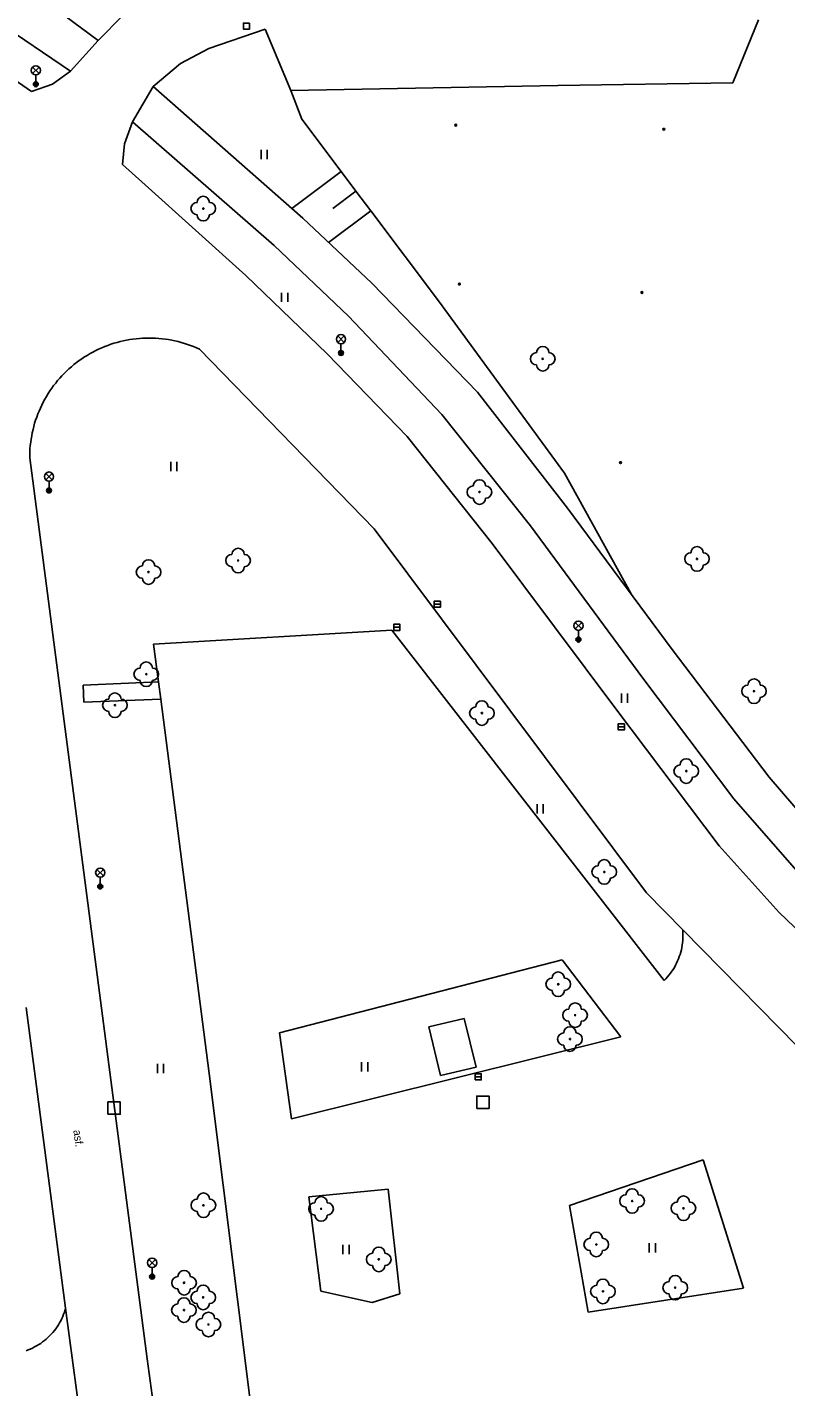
# Model space of a CAD drawing. Extents: x -641829 to -641525, y -1114855 to -1114359.
# Drawn here: x -641724.9 to -641663.2, y -1114535.8 to -1114425.4 of the extents above; entities that cross this region are included whole.
import ezdxf

# ---------------------------------------------------------------- set-up
doc = ezdxf.new("R2010")
doc.units = 0
for name, color, linetype in [('Vrstva 10', 7, 'Continuous'), ('Vrstva 11', 7, 'Continuous'), ('Vrstva 14', 7, 'Continuous'), ('Vrstva 15', 7, 'Continuous'), ('Vrstva 20', 7, 'Continuous'), ('Vrstva 22', 7, 'Continuous'), ('Vrstva 26', 7, 'Continuous'), ('Vrstva 27', 7, 'Continuous'), ('Vrstva 33', 7, 'Continuous'), ('Vrstva 36', 7, 'Continuous'), ('Vrstva 40', 7, 'Continuous')]:
    doc.layers.add(name, color=color, linetype=linetype)

msp = doc.modelspace()

# ---------------------------------------------------------------- linework, layer by layer
at = {"layer": 'Vrstva 10'}
for p, q in [((-641719.11, -1114426.51), (-641717.06, -1114424.45)), ((-641665.47, -1114424.84), (-641667.56, -1114429.94)), ((-641705.53, -1114425.59), (-641710.11, -1114427.15)), ((-641703.46, -1114430.56), (-641705.53, -1114425.59)), ((-641730.26, -1114426.67), (-641724.52, -1114430.66)), ((-641721.35, -1114428.99), (-641719.11, -1114426.51)), ((-641710.11, -1114427.15), (-641712.42, -1114428.39)), ((-641722.8, -1114430.06), (-641721.35, -1114428.99)), ((-641712.42, -1114428.39), (-641714.62, -1114430.25)), ((-641724.52, -1114430.66), (-641722.8, -1114430.06)), ((-641716.31, -1114433.12), (-641714.62, -1114430.25)), ((-641681.77, -1114430.17), (-641703.46, -1114430.56)), ((-641667.56, -1114429.94), (-641681.77, -1114430.17)), ((-641716.31, -1114433.12), (-641716.95, -1114434.91)), ((-641716.95, -1114434.91), (-641717.11, -1114436.59)), ((-641717.11, -1114436.59), (-641715.27, -1114438.22)), ((-641715.27, -1114438.22), (-641707.1, -1114445.6)), ((-641707.1, -1114445.6), (-641700.5, -1114451.95)), ((-641718.57, -1114451.37), (-641718.81, -1114451.47)), ((-641718.32, -1114451.27), (-641718.57, -1114451.37)), ((-641718.08, -1114451.18), (-641718.32, -1114451.27)), ((-641717.82, -1114451.1), (-641718.08, -1114451.18)), ((-641717.57, -1114451.03), (-641717.82, -1114451.1)), ((-641717.31, -1114450.96), (-641717.57, -1114451.03)), ((-641717.06, -1114450.9), (-641717.31, -1114450.96)), ((-641716.8, -1114450.85), (-641717.06, -1114450.9)), ((-641716.54, -1114450.8), (-641716.8, -1114450.85)), ((-641716.28, -1114450.76), (-641716.54, -1114450.8)), ((-641716.02, -1114450.73), (-641716.28, -1114450.76)), ((-641715.75, -1114450.7), (-641716.02, -1114450.73)), ((-641715.49, -1114450.69), (-641715.75, -1114450.7)), ((-641715.23, -1114450.68), (-641715.49, -1114450.69)), ((-641714.96, -1114450.67), (-641715.23, -1114450.68)), ((-641714.7, -1114450.68), (-641714.96, -1114450.67)), ((-641714.43, -1114450.69), (-641714.7, -1114450.68)), ((-641714.17, -1114450.7), (-641714.43, -1114450.69)), ((-641713.91, -1114450.73), (-641714.17, -1114450.7)), ((-641713.64, -1114450.76), (-641713.91, -1114450.73)), ((-641713.38, -1114450.8), (-641713.64, -1114450.76)), ((-641713.12, -1114450.85), (-641713.38, -1114450.8)), ((-641712.86, -1114450.9), (-641713.12, -1114450.85)), ((-641712.61, -1114450.96), (-641712.86, -1114450.9)), ((-641712.35, -1114451.03), (-641712.61, -1114450.96)), ((-641712.1, -1114451.11), (-641712.35, -1114451.03)), ((-641711.85, -1114451.19), (-641712.1, -1114451.11)), ((-641711.6, -1114451.27), (-641711.85, -1114451.19)), ((-641711.35, -1114451.37), (-641711.6, -1114451.27)), ((-641711.11, -1114451.47), (-641711.35, -1114451.37)), ((-641720.65, -1114452.51), (-641720.86, -1114452.67)), ((-641720.43, -1114452.36), (-641720.65, -1114452.51)), ((-641720.21, -1114452.21), (-641720.43, -1114452.36)), ((-641719.99, -1114452.08), (-641720.21, -1114452.21)), ((-641719.76, -1114451.94), (-641719.99, -1114452.08)), ((-641719.53, -1114451.81), (-641719.76, -1114451.94)), ((-641719.29, -1114451.69), (-641719.53, -1114451.81)), ((-641719.06, -1114451.58), (-641719.29, -1114451.69)), ((-641718.81, -1114451.47), (-641719.06, -1114451.58)), ((-641710.87, -1114451.58), (-641711.11, -1114451.47)), ((-641710.87, -1114451.58), (-641696.68, -1114466.16)), ((-641700.5, -1114451.95), (-641694, -1114458.66)), ((-641721.85, -1114453.54), (-641722.04, -1114453.73)), ((-641721.66, -1114453.36), (-641721.85, -1114453.54)), ((-641721.47, -1114453.18), (-641721.66, -1114453.36)), ((-641721.27, -1114453), (-641721.47, -1114453.18)), ((-641721.07, -1114452.83), (-641721.27, -1114453)), ((-641720.86, -1114452.67), (-641721.07, -1114452.83)), ((-641722.87, -1114454.75), (-641723.02, -1114454.97)), ((-641722.72, -1114454.54), (-641722.87, -1114454.75)), ((-641722.55, -1114454.33), (-641722.72, -1114454.54)), ((-641722.39, -1114454.13), (-641722.55, -1114454.33)), ((-641722.21, -1114453.93), (-641722.39, -1114454.13)), ((-641722.04, -1114453.73), (-641722.21, -1114453.93)), ((-641723.44, -1114455.65), (-641723.56, -1114455.88)), ((-641723.3, -1114455.42), (-641723.44, -1114455.65)), ((-641723.17, -1114455.19), (-641723.3, -1114455.42)), ((-641723.02, -1114454.97), (-641723.17, -1114455.19)), ((-641724, -1114456.84), (-641724.09, -1114457.09)), ((-641723.9, -1114456.6), (-641724, -1114456.84)), ((-641723.79, -1114456.36), (-641723.9, -1114456.6)), ((-641723.68, -1114456.12), (-641723.79, -1114456.36)), ((-641723.56, -1114455.88), (-641723.68, -1114456.12)), ((-641724.33, -1114457.85), (-641724.39, -1114458.1)), ((-641724.26, -1114457.59), (-641724.33, -1114457.85)), ((-641724.18, -1114457.34), (-641724.26, -1114457.59)), ((-641724.09, -1114457.09), (-641724.18, -1114457.34)), ((-641724.58, -1114459.14), (-641724.61, -1114459.4)), ((-641724.55, -1114458.88), (-641724.58, -1114459.14)), ((-641724.5, -1114458.62), (-641724.55, -1114458.88)), ((-641724.45, -1114458.36), (-641724.5, -1114458.62)), ((-641724.39, -1114458.1), (-641724.45, -1114458.36)), ((-641694, -1114458.66), (-641687.1, -1114467.37)), ((-641724.65, -1114459.93), (-641724.66, -1114460.2)), ((-641724.66, -1114460.2), (-641724.66, -1114460.41)), ((-641724.64, -1114459.67), (-641724.65, -1114459.93)), ((-641724.61, -1114459.4), (-641724.64, -1114459.67)), ((-641715.11, -1114533.57), (-641724.66, -1114460.41)), ((-641696.68, -1114466.16), (-641674.57, -1114495.73)), ((-641687.1, -1114467.37), (-641676.97, -1114480.89)), ((-641695.26, -1114474.39), (-641714.6, -1114475.54)), ((-641673.13, -1114502.84), (-641695.26, -1114474.39)), ((-641714.6, -1114475.54), (-641714.2, -1114478.59)), ((-641714.2, -1114478.59), (-641714.02, -1114479.99)), ((-641714.02, -1114479.99), (-641710.09, -1114510.39)), ((-641676.97, -1114480.89), (-641668.66, -1114491.92)), ((-641668.66, -1114491.92), (-641663.78, -1114497.32)), ((-641674.57, -1114495.73), (-641671.62, -1114498.73)), ((-641663.78, -1114497.32), (-641659.26, -1114501.67)), ((-641671.62, -1114498.73), (-641659.47, -1114511.09)), ((-641671.61, -1114498.82), (-641671.62, -1114498.73)), ((-641671.6, -1114499.01), (-641671.61, -1114498.82)), ((-641671.69, -1114500.16), (-641671.66, -1114499.97)), ((-641671.66, -1114499.97), (-641671.63, -1114499.78)), ((-641671.63, -1114499.78), (-641671.61, -1114499.59)), ((-641671.61, -1114499.59), (-641671.6, -1114499.4)), ((-641671.6, -1114499.2), (-641671.6, -1114499.01)), ((-641671.6, -1114499.4), (-641671.6, -1114499.2)), ((-641672.04, -1114501.26), (-641671.97, -1114501.09)), ((-641671.97, -1114501.09), (-641671.9, -1114500.9)), ((-641671.9, -1114500.9), (-641671.84, -1114500.72)), ((-641671.84, -1114500.72), (-641671.78, -1114500.54)), ((-641671.78, -1114500.54), (-641671.73, -1114500.35)), ((-641671.73, -1114500.35), (-641671.69, -1114500.16)), ((-641681.41, -1114501.18), (-641704.38, -1114507.1)), ((-641676.64, -1114507.41), (-641681.41, -1114501.18)), ((-641672.62, -1114502.26), (-641672.51, -1114502.1)), ((-641672.51, -1114502.1), (-641672.4, -1114501.94)), ((-641672.4, -1114501.94), (-641672.3, -1114501.78)), ((-641672.3, -1114501.78), (-641672.21, -1114501.61)), ((-641672.21, -1114501.61), (-641672.12, -1114501.44)), ((-641672.12, -1114501.44), (-641672.04, -1114501.26)), ((-641673.13, -1114502.84), (-641672.99, -1114502.7)), ((-641672.99, -1114502.7), (-641672.86, -1114502.56)), ((-641672.86, -1114502.56), (-641672.74, -1114502.41)), ((-641672.74, -1114502.41), (-641672.62, -1114502.26)), ((-641724.95, -1114505.04), (-641721.74, -1114529.44)), ((-641704.38, -1114507.1), (-641703.4, -1114514.07)), ((-641676.64, -1114507.41), (-641703.4, -1114514.07)), ((-641710.09, -1114510.39), (-641706.68, -1114537.6)), ((-641680.82, -1114521.12), (-641669.95, -1114517.42)), ((-641669.95, -1114517.42), (-641666.68, -1114527.82)), ((-641695.55, -1114519.79), (-641701.99, -1114520.4)), ((-641694.6, -1114528.3), (-641695.55, -1114519.79)), ((-641701.99, -1114520.4), (-641701.01, -1114528.06)), ((-641679.29, -1114529.77), (-641680.82, -1114521.12)), ((-641701.01, -1114528.06), (-641696.85, -1114528.99)), ((-641696.85, -1114528.99), (-641694.6, -1114528.3)), ((-641679.29, -1114529.77), (-641666.68, -1114527.82)), ((-641721.91, -1114529.95), (-641721.84, -1114529.77)), ((-641721.84, -1114529.77), (-641721.79, -1114529.58)), ((-641721.79, -1114529.58), (-641721.74, -1114529.44)), ((-641720.22, -1114541.01), (-641721.74, -1114529.44)), ((-641722.44, -1114530.96), (-641722.33, -1114530.8)), ((-641722.33, -1114530.8), (-641722.24, -1114530.64)), ((-641722.24, -1114530.64), (-641722.14, -1114530.47)), ((-641722.14, -1114530.47), (-641722.06, -1114530.3)), ((-641722.06, -1114530.3), (-641721.98, -1114530.12)), ((-641721.98, -1114530.12), (-641721.91, -1114529.95)), ((-641723.47, -1114532.08), (-641723.32, -1114531.96)), ((-641723.32, -1114531.96), (-641723.18, -1114531.83)), ((-641723.18, -1114531.83), (-641723.04, -1114531.7)), ((-641723.04, -1114531.7), (-641722.91, -1114531.56)), ((-641722.91, -1114531.56), (-641722.78, -1114531.42)), ((-641722.78, -1114531.42), (-641722.66, -1114531.27)), ((-641722.66, -1114531.27), (-641722.55, -1114531.12)), ((-641722.55, -1114531.12), (-641722.44, -1114530.96)), ((-641724.96, -1114532.91), (-641724.78, -1114532.84)), ((-641724.78, -1114532.84), (-641724.61, -1114532.77)), ((-641724.61, -1114532.77), (-641724.43, -1114532.69)), ((-641724.43, -1114532.69), (-641724.26, -1114532.6)), ((-641724.26, -1114532.6), (-641724.1, -1114532.51)), ((-641724.1, -1114532.51), (-641723.93, -1114532.41)), ((-641723.93, -1114532.41), (-641723.77, -1114532.31)), ((-641723.77, -1114532.31), (-641723.62, -1114532.2)), ((-641723.62, -1114532.2), (-641723.47, -1114532.08)), ((-641710.95, -1114564.98), (-641715.11, -1114533.57))]:
    msp.add_line(p, q, dxfattribs=at)
at = {"layer": 'Vrstva 11'}
for p, q in [((-641721.35, -1114428.99), (-641733.03, -1114421.08)), ((-641719.11, -1114426.51), (-641724.4, -1114422.58)), ((-641702.47, -1114440.95), (-641714.62, -1114430.25)), ((-641704.8, -1114443.15), (-641716.31, -1114433.12)), ((-641696.86, -1114446.22), (-641702.47, -1114440.95)), ((-641698.78, -1114448.89), (-641704.8, -1114443.15)), ((-641688.28, -1114455.08), (-641696.86, -1114446.22)), ((-641691.19, -1114456.88), (-641698.78, -1114448.89)), ((-641680.98, -1114464.5), (-641688.28, -1114455.08)), ((-641683.99, -1114465.91), (-641691.19, -1114456.88)), ((-641672.47, -1114475.96), (-641680.98, -1114464.5)), ((-641674.85, -1114478.28), (-641683.99, -1114465.91)), ((-641664.6, -1114486.32), (-641672.47, -1114475.96)), ((-641714.2, -1114478.59), (-641720.33, -1114478.85)), ((-641720.27, -1114480.25), (-641720.33, -1114478.85)), ((-641667.48, -1114488.09), (-641674.85, -1114478.28)), ((-641714.02, -1114479.99), (-641720.27, -1114480.25)), ((-641660.12, -1114491.55), (-641664.6, -1114486.32)), ((-641662.19, -1114494.13), (-641667.48, -1114488.09)), ((-641689.36, -1114505.94), (-641692.24, -1114506.62)), ((-641692.24, -1114506.62), (-641691.29, -1114510.56)), ((-641689.36, -1114505.94), (-641688.41, -1114509.88)), ((-641688.41, -1114509.88), (-641691.29, -1114510.56))]:
    msp.add_line(p, q, dxfattribs=at)
at = {"layer": 'Vrstva 14'}
for p, q in [((-641702.56, -1114432.89), (-641703.46, -1114430.56)), ((-641699.36, -1114437.15), (-641702.56, -1114432.89)), ((-641698.16, -1114438.74), (-641699.36, -1114437.15)), ((-641696.96, -1114440.34), (-641698.16, -1114438.74)), ((-641691.47, -1114447.64), (-641696.96, -1114440.34)), ((-641681.21, -1114461.64), (-641691.47, -1114447.64)), ((-641675.82, -1114471.45), (-641681.21, -1114461.64))]:
    msp.add_line(p, q, dxfattribs=at)
at = {"layer": 'Vrstva 15'}
for p, q in [((-641703.37, -1114440.16), (-641699.36, -1114437.15)), ((-641700.04, -1114440.16), (-641698.16, -1114438.74)), ((-641700.38, -1114442.91), (-641696.96, -1114440.34))]:
    msp.add_line(p, q, dxfattribs=at)
at = {"layer": 'Vrstva 20'}
for centre, radius in [((-641690.06, -1114433.39), 0.075), ((-641690.06, -1114433.39), 0.0204), ((-641673.16, -1114433.72), 0.075), ((-641673.16, -1114433.72), 0.0204), ((-641689.76, -1114446.29), 0.075), ((-641689.76, -1114446.29), 0.0204), ((-641674.93, -1114446.97), 0.075), ((-641674.93, -1114446.97), 0.0204), ((-641676.67, -1114460.79), 0.075), ((-641676.67, -1114460.79), 0.0204)]:
    msp.add_circle(centre, radius, dxfattribs=at)
at = {"layer": 'Vrstva 22'}
for centre in [(-641710.56, -1114440.16), (-641682.99, -1114452.36), (-641688.13, -1114463.18), (-641707.73, -1114468.74), (-641670.46, -1114468.61), (-641715.01, -1114469.68), (-641715.19, -1114477.97), (-641665.83, -1114479.35), (-641717.74, -1114480.49), (-641687.93, -1114481.13), (-641671.33, -1114485.84), (-641677.99, -1114494.03), (-641681.73, -1114503.15), (-641680.36, -1114505.66), (-641680.78, -1114507.6), (-641675.73, -1114520.75), (-641710.55, -1114521.1), (-641700.99, -1114521.39), (-641671.56, -1114521.34), (-641678.64, -1114524.28), (-641696.31, -1114525.49), (-641712.12, -1114527.39), (-641710.57, -1114528.58), (-641678.1, -1114528.09), (-641672.23, -1114527.79), (-641712.13, -1114529.61), (-641710.14, -1114530.78)]:
    msp.add_circle(centre, 0.05, dxfattribs=at)
for centre, start, end in [((-641710.56, -1114439.66), 0, 180), ((-641711.06, -1114440.16), 90, 270), ((-641710.06, -1114440.16), 270, 90), ((-641710.56, -1114440.66), 180, 0), ((-641682.99, -1114451.86), 0, 180), ((-641683.49, -1114452.36), 90, 270), ((-641682.49, -1114452.36), 270, 90), ((-641682.99, -1114452.86), 180, 0), ((-641688.13, -1114462.68), 0, 180), ((-641688.63, -1114463.18), 90, 270), ((-641687.63, -1114463.18), 270, 90), ((-641688.13, -1114463.68), 180, 0), ((-641707.73, -1114468.24), 0, 180), ((-641670.46, -1114468.11), 0, 180), ((-641715.01, -1114469.18), 0, 180), ((-641708.23, -1114468.74), 90, 270), ((-641707.23, -1114468.74), 270, 90), ((-641670.96, -1114468.61), 90, 270), ((-641670.46, -1114469.11), 180, 0), ((-641669.96, -1114468.61), 270, 90), ((-641715.51, -1114469.68), 90, 270), ((-641715.01, -1114470.18), 180, 0), ((-641714.51, -1114469.68), 270, 90), ((-641707.73, -1114469.24), 180, 0), ((-641715.69, -1114477.97), 90, 270), ((-641715.19, -1114477.47), 0, 180), ((-641714.69, -1114477.97), 270, 90), ((-641715.19, -1114478.47), 180, 0), ((-641666.33, -1114479.35), 90, 270), ((-641665.83, -1114478.85), 0, 180), ((-641665.33, -1114479.35), 270, 90), ((-641718.24, -1114480.49), 90, 270), ((-641717.74, -1114479.99), 0, 180), ((-641717.24, -1114480.49), 270, 90), ((-641687.93, -1114480.63), 0, 180), ((-641665.83, -1114479.85), 180, 0), ((-641717.74, -1114480.99), 180, 0), ((-641688.43, -1114481.13), 90, 270), ((-641687.43, -1114481.13), 270, 90), ((-641687.93, -1114481.63), 180, 0), ((-641671.83, -1114485.84), 90, 270), ((-641671.33, -1114485.34), 0, 180), ((-641670.83, -1114485.84), 270, 90), ((-641671.33, -1114486.34), 180, 0), ((-641677.99, -1114493.53), 0, 180), ((-641678.49, -1114494.03), 90, 270), ((-641677.49, -1114494.03), 270, 90), ((-641677.99, -1114494.53), 180, 0), ((-641681.73, -1114502.65), 0, 180), ((-641682.23, -1114503.15), 90, 270), ((-641681.23, -1114503.15), 270, 90), ((-641681.73, -1114503.65), 180, 0), ((-641680.86, -1114505.66), 90, 270), ((-641680.36, -1114505.16), 0, 180), ((-641679.86, -1114505.66), 270, 90), ((-641680.78, -1114507.1), 0, 180), ((-641680.36, -1114506.16), 180, 0), ((-641681.28, -1114507.6), 90, 270), ((-641680.28, -1114507.6), 270, 90), ((-641680.78, -1114508.1), 180, 0), ((-641675.73, -1114520.25), 0, 180), ((-641711.05, -1114521.1), 90, 270), ((-641710.55, -1114520.6), 0, 180), ((-641710.05, -1114521.1), 270, 90), ((-641701.49, -1114521.39), 90, 270), ((-641700.99, -1114520.89), 0, 180), ((-641700.49, -1114521.39), 270, 90), ((-641676.23, -1114520.75), 90, 270), ((-641675.23, -1114520.75), 270, 90), ((-641672.06, -1114521.34), 90, 270), ((-641671.56, -1114520.84), 0, 180), ((-641671.06, -1114521.34), 270, 90), ((-641710.55, -1114521.6), 180, 0), ((-641700.99, -1114521.89), 180, 0), ((-641675.73, -1114521.25), 180, 0), ((-641671.56, -1114521.84), 180, 0), ((-641679.14, -1114524.28), 90, 270), ((-641678.64, -1114523.78), 0, 180), ((-641678.14, -1114524.28), 270, 90), ((-641696.81, -1114525.49), 90, 270), ((-641696.31, -1114524.99), 0, 180), ((-641695.81, -1114525.49), 270, 90), ((-641678.64, -1114524.78), 180, 0), ((-641712.12, -1114526.89), 0, 180), ((-641696.31, -1114525.99), 180, 0), ((-641712.62, -1114527.39), 90, 270), ((-641711.62, -1114527.39), 270, 90), ((-641710.57, -1114528.08), 0, 180), ((-641678.6, -1114528.09), 90, 270), ((-641678.1, -1114527.59), 0, 180), ((-641677.6, -1114528.09), 270, 90), ((-641672.73, -1114527.79), 90, 270), ((-641672.23, -1114527.29), 0, 180), ((-641671.73, -1114527.79), 270, 90), ((-641712.13, -1114529.11), 0, 180), ((-641712.12, -1114527.89), 180, 0), ((-641711.07, -1114528.58), 90, 270), ((-641710.07, -1114528.58), 270, 90), ((-641678.1, -1114528.59), 180, 0), ((-641672.23, -1114528.29), 180, 0), ((-641712.63, -1114529.61), 90, 270), ((-641711.63, -1114529.61), 270, 90), ((-641710.57, -1114529.08), 180, 0), ((-641710.14, -1114530.28), 0, 180), ((-641712.13, -1114530.11), 180, 0), ((-641710.64, -1114530.78), 90, 270), ((-641709.64, -1114530.78), 270, 90), ((-641710.14, -1114531.28), 180, 0)]:
    msp.add_arc(centre, 0.5, start, end, dxfattribs=at)
at = {"layer": 'Vrstva 26'}
for points in [[(-641718.31, -1114513.7), (-641717.31, -1114513.7), (-641717.31, -1114512.7), (-641718.31, -1114512.7)], [(-641688.35, -1114513.23), (-641687.35, -1114513.23), (-641687.35, -1114512.23), (-641688.35, -1114512.23)]]:
    msp.add_lwpolyline(points, close=True, dxfattribs=at)
at = {"layer": 'Vrstva 27'}
for p, q in [((-641691.3, -1114472.29), (-641691.8, -1114472.29)), ((-641695.09, -1114474.16), (-641694.59, -1114474.16)), ((-641676.36, -1114482.25), (-641676.86, -1114482.25)), ((-641688.48, -1114510.67), (-641687.98, -1114510.67))]:
    msp.add_line(p, q, dxfattribs=at)
for points in [[(-641706.8, -1114425.09), (-641707.3, -1114425.09), (-641707.3, -1114425.59), (-641706.8, -1114425.59)], [(-641691.3, -1114472.04), (-641691.8, -1114472.04), (-641691.8, -1114472.54), (-641691.3, -1114472.54)], [(-641695.09, -1114474.41), (-641694.59, -1114474.41), (-641694.59, -1114473.91), (-641695.09, -1114473.91)], [(-641676.36, -1114482), (-641676.86, -1114482), (-641676.86, -1114482.5), (-641676.36, -1114482.5)], [(-641688.48, -1114510.92), (-641687.98, -1114510.92), (-641687.98, -1114510.42), (-641688.48, -1114510.42)]]:
    msp.add_lwpolyline(points, close=True, dxfattribs=at)
at = {"layer": 'Vrstva 33'}
for p, q in [((-641724.424, -1114429.2), (-641723.896, -1114428.67)), ((-641724.424, -1114428.67), (-641723.896, -1114429.2)), ((-641724.16, -1114429.31), (-641724.16, -1114430.06)), ((-641699.644, -1114451.03), (-641699.116, -1114450.5)), ((-641699.644, -1114450.5), (-641699.116, -1114451.03)), ((-641699.38, -1114451.14), (-641699.38, -1114451.89)), ((-641723.356, -1114462.19), (-641722.824, -1114461.66)), ((-641723.356, -1114461.66), (-641722.824, -1114462.19)), ((-641723.09, -1114462.3), (-641723.09, -1114463.05)), ((-641680.354, -1114474.3), (-641679.826, -1114473.77)), ((-641680.354, -1114473.77), (-641679.826, -1114474.3)), ((-641680.09, -1114474.41), (-641680.09, -1114475.16)), ((-641719.196, -1114494.35), (-641718.664, -1114493.82)), ((-641719.196, -1114493.82), (-641718.664, -1114494.35)), ((-641718.93, -1114494.46), (-641718.93, -1114495.21)), ((-641714.984, -1114526.03), (-641714.456, -1114525.5)), ((-641714.984, -1114525.5), (-641714.456, -1114526.03)), ((-641714.72, -1114526.14), (-641714.72, -1114526.89))]:
    msp.add_line(p, q, dxfattribs=at)
for centre, radius in [((-641724.16, -1114428.935), 0.375), ((-641724.16, -1114430.06), 0.2), ((-641724.16, -1114430.06), 0.145), ((-641724.16, -1114430.06), 0.0876), ((-641699.38, -1114450.765), 0.375), ((-641699.38, -1114451.89), 0.2), ((-641699.38, -1114451.89), 0.145), ((-641699.38, -1114451.89), 0.0876), ((-641723.09, -1114461.925), 0.375), ((-641723.09, -1114463.05), 0.2), ((-641723.09, -1114463.05), 0.145), ((-641723.09, -1114463.05), 0.0876), ((-641680.09, -1114474.035), 0.375), ((-641680.09, -1114475.16), 0.2), ((-641680.09, -1114475.16), 0.145), ((-641680.09, -1114475.16), 0.0876), ((-641718.93, -1114494.085), 0.375), ((-641718.93, -1114495.21), 0.2), ((-641718.93, -1114495.21), 0.145), ((-641718.93, -1114495.21), 0.0876), ((-641714.72, -1114525.765), 0.375), ((-641714.72, -1114526.89), 0.2), ((-641714.72, -1114526.89), 0.145), ((-641714.72, -1114526.89), 0.0876)]:
    msp.add_circle(centre, radius, dxfattribs=at)
at = {"layer": 'Vrstva 36'}
for p, q in [((-641705.864, -1114436.142), (-641705.864, -1114435.394)), ((-641705.364, -1114436.142), (-641705.364, -1114435.394)), ((-641704.204, -1114447.742), (-641704.204, -1114446.994)), ((-641703.704, -1114447.742), (-641703.704, -1114446.994)), ((-641713.204, -1114461.484), (-641713.204, -1114460.732)), ((-641712.704, -1114461.484), (-641712.704, -1114460.732)), ((-641676.604, -1114480.284), (-641676.604, -1114479.532)), ((-641676.104, -1114480.284), (-641676.104, -1114479.532)), ((-641683.444, -1114489.274), (-641683.444, -1114488.522)), ((-641682.944, -1114489.274), (-641682.944, -1114488.522)), ((-641714.294, -1114510.362), (-641714.294, -1114509.614)), ((-641713.794, -1114510.362), (-641713.794, -1114509.614)), ((-641697.704, -1114510.222), (-641697.704, -1114509.474)), ((-641697.204, -1114510.222), (-641697.204, -1114509.474)), ((-641674.334, -1114524.932), (-641674.334, -1114524.184)), ((-641673.834, -1114524.932), (-641673.834, -1114524.184)), ((-641699.214, -1114525.074), (-641699.214, -1114524.322)), ((-641698.714, -1114525.074), (-641698.714, -1114524.322))]:
    msp.add_line(p, q, dxfattribs=at)

# ---------------------------------------------------------------- texts
at = {"layer": 'Vrstva 40'}
msp.add_text('asf.', height=0.65, rotation=277.47848, dxfattribs=at).set_placement((-641721.12, -1114515.01))

doc.saveas('drawing.dxf')
